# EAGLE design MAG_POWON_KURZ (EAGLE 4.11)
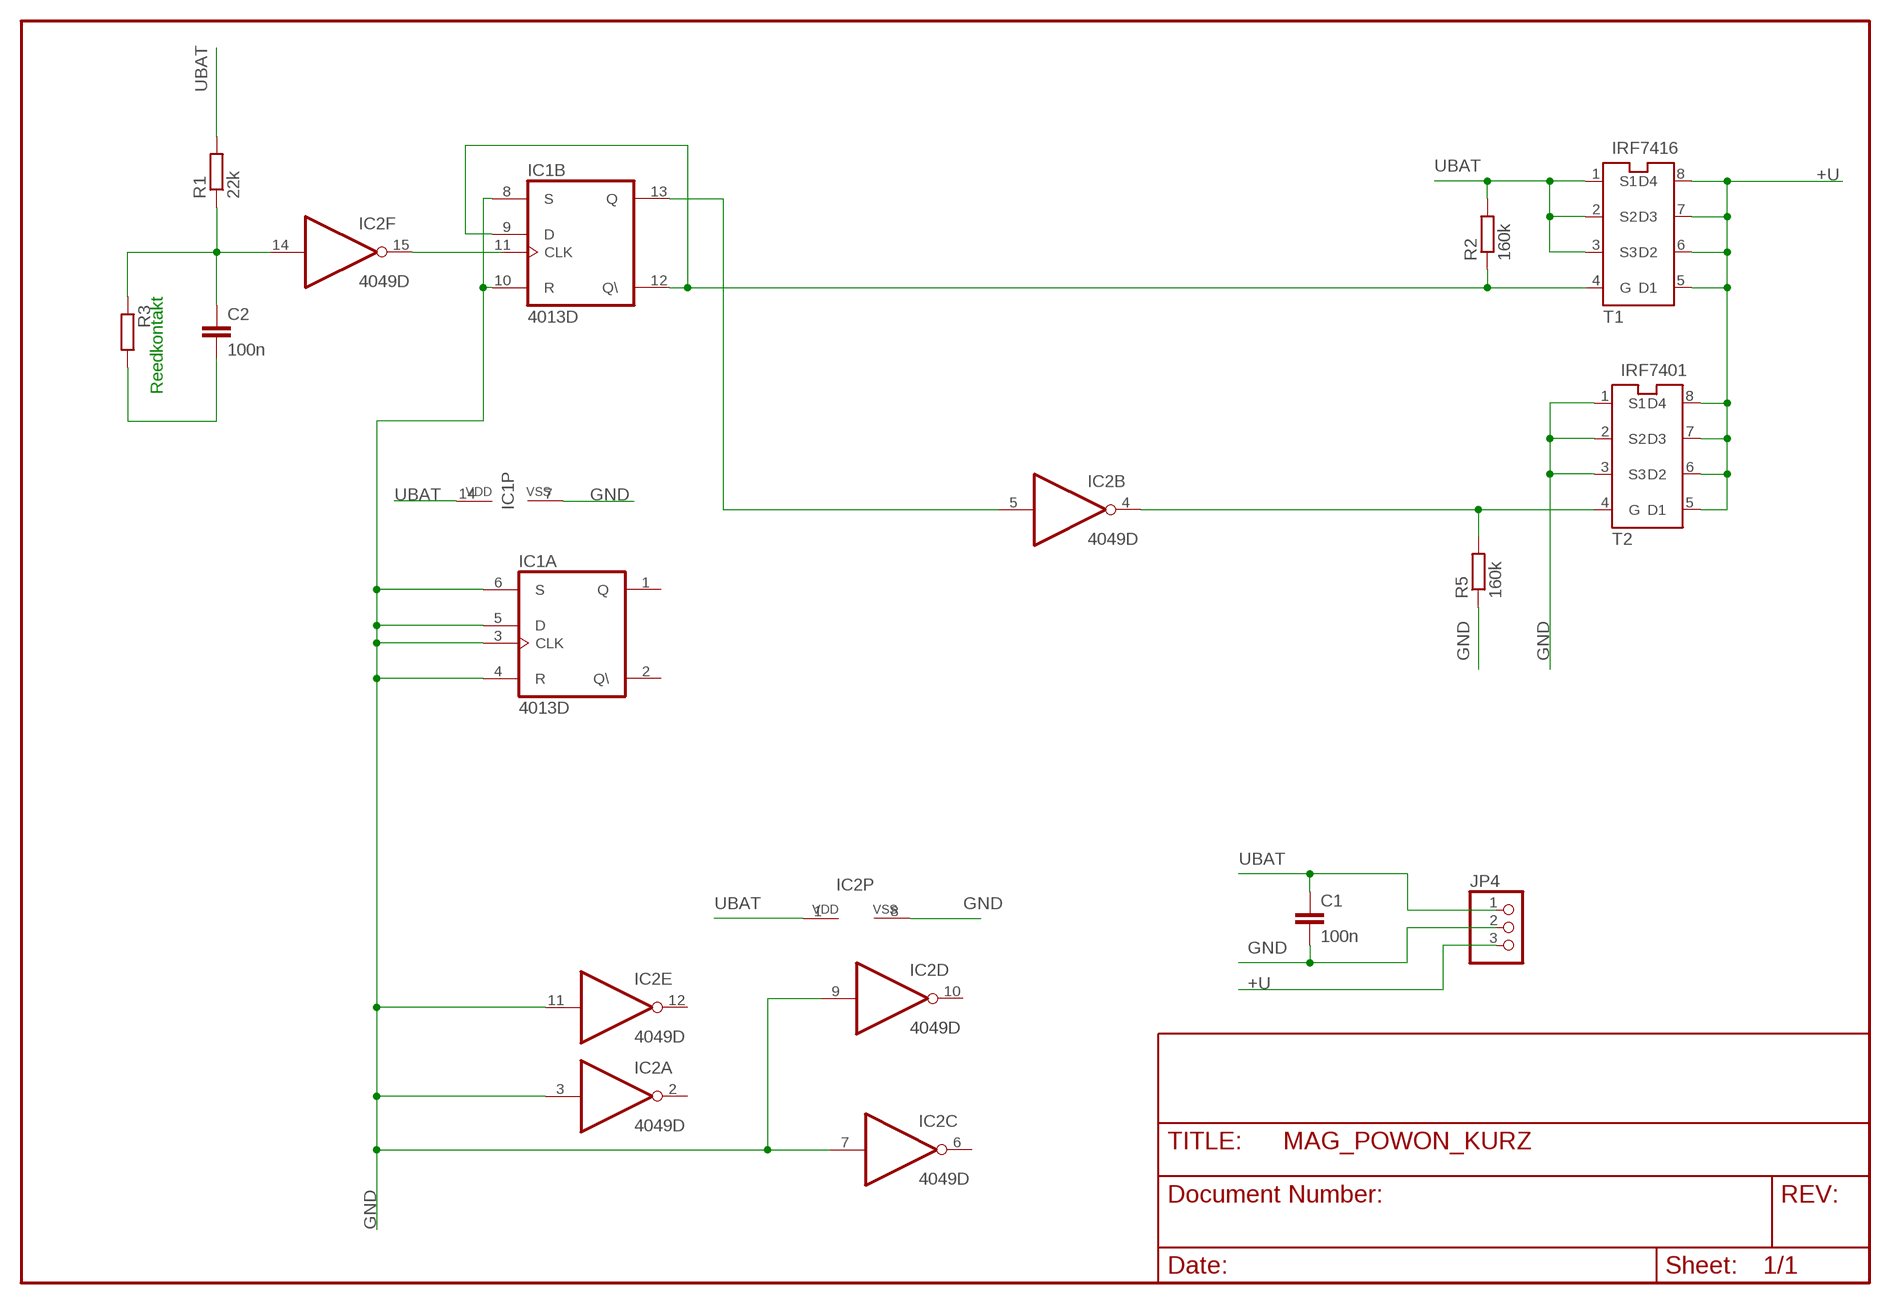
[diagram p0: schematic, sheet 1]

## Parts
C1  100n  C-EUC0805  [C0805]
C2  100n  C-EUC0805  [C0805]
IC1  4013D  [SO14]
IC2  4049D  [SO16]
JP4  PINHD-1X3  [1X03]
R1  22k  R-EU_R0805  [R0805]
R2  160k  R-EU_R0805  [R0805]
R3  R-EU_0411/15  [0411/15]
R5  160k  R-EU_R0805  [R0805]
T1  IRF7416  SI4425  [SO-8]
T2  IRF7401  SI4425  [SO-8]

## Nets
+U: JP4.3 T1.5(D1) T1.6(D2) T1.7(D3) T1.8(D4) T2.5(D1) T2.6(D2) T2.7(D3) T2.8(D4)
GND: C1.2 C2.2 IC1.3(A:CLK) IC1.4(A:R) IC1.5(A:D) IC1.6(A:S) IC1.7(P:VSS) IC1.8(B:S) IC1.10(B:R) IC2.3(A:I) IC2.7(C:I) IC2.8(P:VSS) IC2.9(D:I) IC2.11(E:I) JP4.2 R3.2 R5.1 T2.1(S1) T2.2(S2) T2.3(S3)
N$1: C2.1 IC2.14(F:I) R1.1 R3.1
N$3: IC1.13(B:Q) IC2.5(B:I)
N$4: IC1.9(B:D) IC1.12(B:Q\) R2.1 T1.4(G)
N$5: IC1.11(B:CLK) IC2.15(F:O)
N$8: IC2.4(B:O) R5.2 T2.4(G)
UBAT: C1.1 IC1.14(P:VDD) IC2.1(P:VDD) JP4.1 R1.2 R2.2 T1.1(S1) T1.2(S2) T1.3(S3)
Unconnected: IC1.1(A:Q) IC1.2(A:Q\) IC2.2(A:O) IC2.6(C:O) IC2.10(D:O) IC2.12(E:O)

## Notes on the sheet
- Reedkontakt

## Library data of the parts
C1 C2 = rcl:C-EU: CAPACITOR, European symbol
IC1 = 40xx:4013: Dual D FLIP FLOP, set/reset
IC2 = 40xx:4049: Hex inverting BUFFER
JP4 = pinhead:PINHD-1X3: PIN HEADER
R1-R3 R5 = rcl:R-EU_: RESISTOR, European symbol
T1 T2 = transistor-fet:SI4425

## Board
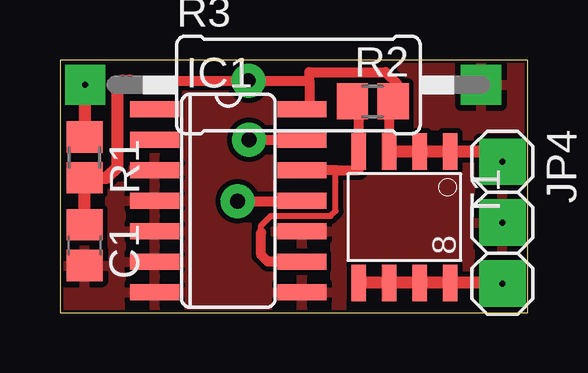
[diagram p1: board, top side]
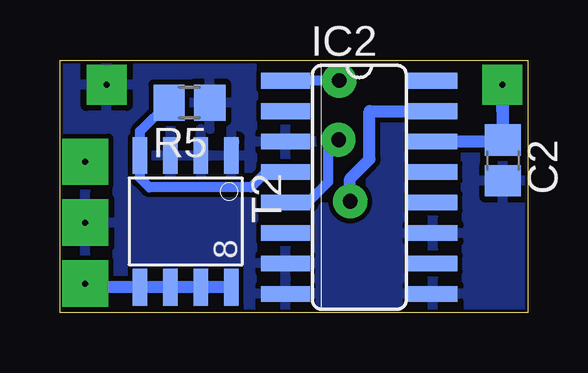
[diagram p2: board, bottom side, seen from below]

Size 19.51 x 10.53 mm. Coordinates in mm from the lower left corner, seen from the top.
Outline: 0,0 19.51,0 19.51,10.53 0,10.53 0,0
Copper layers (1*16): Top 0.035mm / dielectric 1.5mm / Bottom 0.035mm
Design rules "default": minimum track width 10mil, minimum drill 24mil, track to track 8mil, track to pad 8mil, pad to pad 8mil, via to via 8mil, smd to smd 8mil, copper to edge 5mil, drill to drill 8mil, minimum pad ring 10mil, minimum via ring 8mil, stop-mask expansion 4mil, vias tented up to drill 0mil, thermal gap 10mil

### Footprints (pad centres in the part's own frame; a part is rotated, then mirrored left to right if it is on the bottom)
C0805 = smd 1.3 x 1.5: 1 -0.85,0; 2 0.85,0
SO14 = smd 0.66 x 2.032: 1 -3.81,-3.073; 2 -2.54,-3.073; 3 -1.27,-3.073; 4 0,-3.073; 5 1.27,-3.073; 6 2.54,-3.073; 7 3.81,-3.073; 8 3.81,3.073; 9 2.54,3.073; 10 1.27,3.073; 11 0,3.073; 12 -1.27,3.073; 13 -2.54,3.073; 14 -3.81,3.073
SO16 = smd 0.66 x 2.032: 1 -4.445,-3.073; 2 -3.175,-3.073; 3 -1.905,-3.073; 4 -0.635,-3.073; 5 0.635,-3.073; 6 1.905,-3.073; 7 3.175,-3.073; 8 4.445,-3.073; 9 4.445,3.073; 10 3.175,3.073; 11 1.905,3.073; 12 0.635,3.073; 13 -0.635,3.073; 14 -1.905,3.073; 15 -3.175,3.073; 16 -4.445,3.073
1X03 = drill 0.254 pad 1.93 square: 1 -2.54,0; 2 0,0; 3 2.54,0
R0805 = smd 1.3 x 1.5: 1 -0.85,0; 2 0.85,0
0411/15 = drill 0.254 pad 1.676 square: 1 -8.89,0; 2 7.62,0
SO-8 = smd 1.524 x 0.61: 1 -2.743,1.27; 2 -2.743,0; 3 -2.743,-1.27; 4 -2.743,-2.54; 5 2.743,-2.54; 6 2.743,-1.27; 7 2.743,0; 8 2.743,1.27

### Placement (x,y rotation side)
C1  1.03,2.81 270 top
C2  1.03,6.35 270 bottom
IC1  7.02,4.67 270 top
IC2  7.02,5.23 270 bottom
JP4  18.45,3.75 270 top
R1  1.03,6.47 270 top
R2  13.04,8.81 0 top
R3  9.94,9.49 0 top
R5  14.11,8.76 180 bottom
T1  15,3.98 270 top
T2  13.63,3.81 270 bottom

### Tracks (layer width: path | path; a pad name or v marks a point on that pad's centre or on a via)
+U
  Top 0.508: JP4.3 17.87,1.24 T1.8 T1.7 T1.6 T1.5
  Bottom 0.508: T2.8 T2.7 T2.6 T2.5 17.82,1.06 18.02,1.21 JP4.3
GND
  Bottom 0.406: T2.1 12.23,7.13
  Bottom 0.508: 13.27,8.73 13.26,8.73 R5.1
  pour Bottom: -0.04,10.66 -0.06,0.02 19.19,0 19.34,10.69
  pour Top: 0.01,10.69 19.29,10.69 19.29,-0.03 0.01,-0.03
N$1
  Top 0.508: R3.1 1.03,9.49 R1.1
  Bottom 0.508: C2.1 R3.1 1.03,9.49 1.03,7.13 IC2.14
N$3  (via drill 0.61 pad 1.42)
  Top 0.406: v7.89,7.21 IC1.13
  Bottom 0.406: 9.18,4.59 8.32,5.46 8.32,6.78 v7.89,7.21
  Bottom 0.508: IC2.5 9.18,4.59
N$4
  Top 0.254: 8.39,3.35 8.39,3.63 8.8,4.03 11.29,4.03 11.49,4.24 11.49,5.94
  Top 0.406: R2.1 12.46,8.81 T1.4 12.46,5.94 11.49,5.94 IC1.12 10.1,5.91 | IC1.9 8.67,2.13 8.39,2.41 8.39,3.35
N$5  (via drill 0.61 pad 1.42)
  Top 0.254: 10.1,4.64 IC1.11
  Top 0.406: v7.4,4.64 10.1,4.64
  Bottom 0.508: IC2.15 6.59,8.4 6.59,6.4 7.4,5.58 v7.4,4.64
N$8
  Bottom 0.406: 10.91,5.86 11.54,5.23 15.79,5.23 16.17,5.61 T2.4 16.17,7.56 R5.2
  Bottom 0.508: IC2.4 10.91,5.86
UBAT  (via drill 0.61 pad 1.42)
  Top 0.406: IC1.14 10.4,8.48 10.4,9.67 | 10.4,9.67 10.4,10.03 13.58,10.03 14.07,9.53 R2.2 13.73,8.8 T1.3 | 10.4,9.67 v7.86,9.67 2.92,9.67
  Top 0.508: T1.3 T1.2 T1.1 18.12,6.73 JP4.1 | 1.03,3.63 C1.1 R1.2 1.93,5.62 2.4,6.09 2.4,9.47 2.6,9.67 2.92,9.67
  Bottom 0.406: v7.86,9.67 IC2.1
